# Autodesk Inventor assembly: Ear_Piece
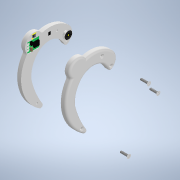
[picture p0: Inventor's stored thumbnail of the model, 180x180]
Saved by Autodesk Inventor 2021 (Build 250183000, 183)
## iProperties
Created: 2021-02
Part Number: Ear_Piece
Document SubType Name: Assembly
Designer: callu
Author: callu
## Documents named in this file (8)
- C:\Users\callu\Downloads\Final Device Cad\Ear_Piece (1).iam
- C:\Users\callu\Downloads\Final Device Cad\Battery.ipt
- C:\Users\callu\Downloads\Final Device Cad\BT_Chip.ipt
- C:\Users\callu\Downloads\Final Device Cad\EARPC_RS.ipt
- C:\Users\callu\Downloads\Final Device Cad\EARPC_LS.ipt
- C:\Users\callu\Downloads\Final Device Cad\Vibration_Motor.ipt
- C:\Users\callu\Downloads\Final Device Cad\Screw.ipt
- C:\Users\callu\Downloads\Final Device Cad\BMX160_Orentation_Sensor.ipt
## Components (9 placed, 7 different names)
1. Battery:1 — Mate:5, Mate:6, Mate:8, Mate:9, Mate:10
2. BT_Chip:1 — Mate:2, Mate:3, Mate:4
3. EARPC_RS:1 — Mate:2, Mate:3, Mate:4, Mate:7, Mate:8, Mate:9, Mate:10, Mate:13, Mate:14, Mate:15, Mate:16
4. EARPC_LS:1 — Mate:1, Mate:5, Mate:6, Mate:11, Mate:12, Mate:16, Mate:17, Flush:1, Flush:2, Flush:19
5. Vibration_Motor:1 — Mate:1, Mate:7
6. Screw:1 — Mate:11, Flush:2
7. Screw:2 — Mate:17, Flush:1
8. Screw:3 — Mate:12, Flush:19
9. BMX160_Orentation_Sensor:1 — Mate:13, Mate:14, Mate:15
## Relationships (20: Mate 17, Flush 3)
- Mate:1: EARPC_LS:1 ↔ Vibration_Motor:1
- Mate:2: BT_Chip:1 ↔ EARPC_RS:1
- Mate:3: BT_Chip:1 ↔ EARPC_RS:1
- Mate:4: BT_Chip:1 ↔ EARPC_RS:1
- Mate:5: Battery:1 ↔ EARPC_LS:1
- Mate:6: Battery:1 ↔ EARPC_LS:1
- Mate:7: EARPC_RS:1 ↔ Vibration_Motor:1
- Mate:8: Battery:1 ↔ EARPC_RS:1
- Mate:9: Battery:1 ↔ EARPC_RS:1
- Mate:10: Battery:1 ↔ EARPC_RS:1
- Mate:11: EARPC_LS:1 ↔ Screw:1
- Mate:12: EARPC_LS:1 ↔ Screw:3
- Mate:13: EARPC_RS:1 ↔ BMX160_Orentation_Sensor:1
- Mate:14: EARPC_RS:1 ↔ BMX160_Orentation_Sensor:1
- Mate:15: EARPC_RS:1 ↔ BMX160_Orentation_Sensor:1
- Mate:16: EARPC_RS:1 ↔ EARPC_LS:1
- Mate:17: EARPC_LS:1 ↔ Screw:2
- Flush:1: EARPC_LS:1 ↔ Screw:2
- Flush:2: EARPC_LS:1 ↔ Screw:1
- Flush:19: EARPC_LS:1 ↔ Screw:3
